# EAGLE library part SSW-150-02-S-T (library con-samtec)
THROUGH-HOLE .025" SQ POST SOCKET Source: Samtec SSW.pdf
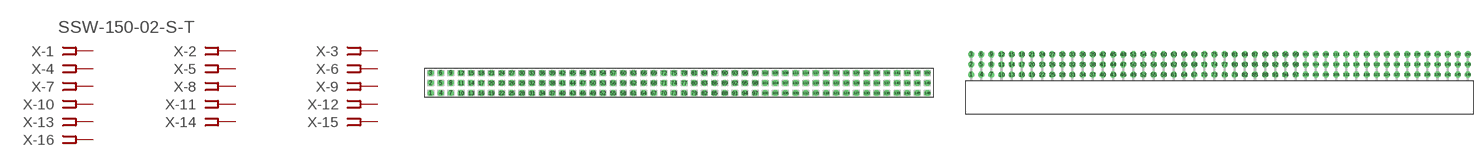
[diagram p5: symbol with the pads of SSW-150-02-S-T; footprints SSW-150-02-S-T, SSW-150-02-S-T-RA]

Designator prefix X; gates -1=FPINV -2=FPIN -3=FPIN -4=FPIN -5=FPIN -6=FPIN -7=FPIN -8=FPIN -9=FPIN -10=FPIN -11=FPIN -12=FPIN -13=FPIN -14=FPIN -15=FPIN -16=FPIN -17=FPIN -18=FPIN -19=FPIN -20=FPIN -21=FPIN -22=FPIN -23=FPIN -24=FPIN -25=FPIN -26=FPIN -27=FPIN -28=FPIN -29=FPIN -30=FPIN -31=FPIN -32=FPIN -33=FPIN -34=FPIN -35=FPIN -36=FPIN -37=FPIN -38=FPIN -39=FPIN -40=FPIN -41=FPIN -42=FPIN -43=FPIN -44=FPIN -45=FPIN -46=FPIN -47=FPIN -48=FPIN -49=FPIN -50=FPIN -51=FPIN -52=FPIN -53=FPIN -54=FPIN -55=FPIN -56=FPIN -57=FPIN -58=FPIN -59=FPIN -60=FPIN -61=FPIN -62=FPIN -63=FPIN -64=FPIN -65=FPIN -66=FPIN -67=FPIN -68=FPIN -69=FPIN -70=FPIN -71=FPIN -72=FPIN -73=FPIN -74=FPIN -75=FPIN -76=FPIN -77=FPIN -78=FPIN -79=FPIN -80=FPIN -81=FPIN -82=FPIN -83=FPIN -84=FPIN -85=FPIN -86=FPIN -87=FPIN -88=FPIN -89=FPIN -90=FPIN -91=FPIN -92=FPIN -93=FPIN -94=FPIN -95=FPIN -96=FPIN -97=FPIN -98=FPIN -99=FPIN -100=FPIN -101=FPIN -102=FPIN -103=FPIN -104=FPIN -105=FPIN -106=FPIN -107=FPIN -108=FPIN -109=FPIN -110=FPIN -111=FPIN -112=FPIN -113=FPIN -114=FPIN -115=FPIN -116=FPIN -117=FPIN -118=FPIN -119=FPIN -120=FPIN -121=FPIN -122=FPIN -123=FPIN -124=FPIN -125=FPIN -126=FPIN -127=FPIN -128=FPIN -129=FPIN -130=FPIN -131=FPIN -132=FPIN -133=FPIN -134=FPIN -135=FPIN -136=FPIN -137=FPIN -138=FPIN -139=FPIN -140=FPIN -141=FPIN -142=FPIN -143=FPIN -144=FPIN -145=FPIN -146=FPIN -147=FPIN -148=FPIN -149=FPIN -150=FPIN

## SSW-150-02-S-T (MPN: SSW-150-02-S-T; OC_FARNELL: unknown; OC_NEWARK: 83P1897)  [SSW-150-02-S-T]
1  -1:1  pas
2  -2:1  pas
3  -3:1  pas
4  -4:1  pas
5  -5:1  pas
6  -6:1  pas
7  -7:1  pas
8  -8:1  pas
9  -9:1  pas
10  -10:1  pas
11  -11:1  pas
12  -12:1  pas
13  -13:1  pas
14  -14:1  pas
15  -15:1  pas
16  -16:1  pas
17  -17:1  pas
18  -18:1  pas
19  -19:1  pas
20  -20:1  pas
21  -21:1  pas
22  -22:1  pas
23  -23:1  pas
24  -24:1  pas
25  -25:1  pas
26  -26:1  pas
27  -27:1  pas
28  -28:1  pas
29  -29:1  pas
30  -30:1  pas
31  -31:1  pas
32  -32:1  pas
33  -33:1  pas
34  -34:1  pas
35  -35:1  pas
36  -36:1  pas
37  -37:1  pas
38  -38:1  pas
39  -39:1  pas
40  -40:1  pas
41  -41:1  pas
42  -42:1  pas
43  -43:1  pas
44  -44:1  pas
45  -45:1  pas
46  -46:1  pas
47  -47:1  pas
48  -48:1  pas
49  -49:1  pas
50  -50:1  pas
51  -51:1  pas
52  -52:1  pas
53  -53:1  pas
54  -54:1  pas
55  -55:1  pas
56  -56:1  pas
57  -57:1  pas
58  -58:1  pas
59  -59:1  pas
60  -60:1  pas
61  -61:1  pas
62  -62:1  pas
63  -63:1  pas
64  -64:1  pas
65  -65:1  pas
66  -66:1  pas
67  -67:1  pas
68  -68:1  pas
69  -69:1  pas
70  -70:1  pas
71  -71:1  pas
72  -72:1  pas
73  -73:1  pas
74  -74:1  pas
75  -75:1  pas
76  -76:1  pas
77  -77:1  pas
78  -78:1  pas
79  -79:1  pas
80  -80:1  pas
81  -81:1  pas
82  -82:1  pas
83  -83:1  pas
84  -84:1  pas
85  -85:1  pas
86  -86:1  pas
87  -87:1  pas
88  -88:1  pas
89  -89:1  pas
90  -90:1  pas
91  -91:1  pas
92  -92:1  pas
93  -93:1  pas
94  -94:1  pas
95  -95:1  pas
96  -96:1  pas
97  -97:1  pas
98  -98:1  pas
99  -99:1  pas
100  -100:1  pas
101  -101:1  pas
102  -102:1  pas
103  -103:1  pas
104  -104:1  pas
105  -105:1  pas
106  -106:1  pas
107  -107:1  pas
108  -108:1  pas
109  -109:1  pas
110  -110:1  pas
111  -111:1  pas
112  -112:1  pas
113  -113:1  pas
114  -114:1  pas
115  -115:1  pas
116  -116:1  pas
117  -117:1  pas
118  -118:1  pas
119  -119:1  pas
120  -120:1  pas
121  -121:1  pas
122  -122:1  pas
123  -123:1  pas
124  -124:1  pas
125  -125:1  pas
126  -126:1  pas
127  -127:1  pas
128  -128:1  pas
129  -129:1  pas
130  -130:1  pas
131  -131:1  pas
132  -132:1  pas
133  -133:1  pas
134  -134:1  pas
135  -135:1  pas
136  -136:1  pas
137  -137:1  pas
138  -138:1  pas
139  -139:1  pas
140  -140:1  pas
141  -141:1  pas
142  -142:1  pas
143  -143:1  pas
144  -144:1  pas
145  -145:1  pas
146  -146:1  pas
147  -147:1  pas
148  -148:1  pas
149  -149:1  pas
150  -150:1  pas

## SSW-150-02-S-TRA (MPN: SSW-150-02-S-T-RA; OC_FARNELL: unknown; OC_NEWARK: 83P1898)  [SSW-150-02-S-T-RA]
Pads as for SSW-150-02-S-T

## Footprint SSW-150-02-S-T (pad centres in mm)
THROUGH-HOLE .025" SQ POST SOCKET Source: Samtec SSW.pdf
drill 1 pad 1.5 octagon: 1 -62.23,-2.54; 2 -62.23,0; 3 -62.23,2.54; 4 -59.69,-2.54; 5 -59.69,0; 6 -59.69,2.54; 7 -57.15,-2.54; 8 -57.15,0; 9 -57.15,2.54; 10 -54.61,-2.54; 11 -54.61,0; 12 -54.61,2.54; 13 -52.07,-2.54; 14 -52.07,0; 15 -52.07,2.54; 16 -49.53,-2.54; 17 -49.53,0; 18 -49.53,2.54; 19 -46.99,-2.54; 20 -46.99,0; 21 -46.99,2.54; 22 -44.45,-2.54; 23 -44.45,0; 24 -44.45,2.54; 25 -41.91,-2.54; 26 -41.91,0; 27 -41.91,2.54; 28 -39.37,-2.54; 29 -39.37,0; 30 -39.37,2.54; 31 -36.83,-2.54; 32 -36.83,0; 33 -36.83,2.54; 34 -34.29,-2.54; 35 -34.29,0; 36 -34.29,2.54; 37 -31.75,-2.54; 38 -31.75,0; 39 -31.75,2.54; 40 -29.21,-2.54; 41 -29.21,0; 42 -29.21,2.54; 43 -26.67,-2.54; 44 -26.67,0; 45 -26.67,2.54; 46 -24.13,-2.54; 47 -24.13,0; 48 -24.13,2.54; 49 -21.59,-2.54; 50 -21.59,0; 51 -21.59,2.54; 52 -19.05,-2.54; 53 -19.05,0; 54 -19.05,2.54; 55 -16.51,-2.54; 56 -16.51,0; 57 -16.51,2.54; 58 -13.97,-2.54; 59 -13.97,0; 60 -13.97,2.54; 61 -11.43,-2.54; 62 -11.43,0; 63 -11.43,2.54; 64 -8.89,-2.54; 65 -8.89,0; 66 -8.89,2.54; 67 -6.35,-2.54; 68 -6.35,0; 69 -6.35,2.54; 70 -3.81,-2.54; 71 -3.81,0; 72 -3.81,2.54; 73 -1.27,-2.54; 74 -1.27,0; 75 -1.27,2.54; 76 1.27,-2.54; 77 1.27,0; 78 1.27,2.54; 79 3.81,-2.54; 80 3.81,0; 81 3.81,2.54; 82 6.35,-2.54; 83 6.35,0; 84 6.35,2.54; 85 8.89,-2.54; 86 8.89,0; 87 8.89,2.54; 88 11.43,-2.54; 89 11.43,0; 90 11.43,2.54; 91 13.97,-2.54; 92 13.97,0; 93 13.97,2.54; 94 16.51,-2.54; 95 16.51,0; 96 16.51,2.54; 97 19.05,-2.54; 98 19.05,0; 99 19.05,2.54; 100 21.59,-2.54; 101 21.59,0; 102 21.59,2.54; 103 24.13,-2.54; 104 24.13,0; 105 24.13,2.54; 106 26.67,-2.54; 107 26.67,0; 108 26.67,2.54; 109 29.21,-2.54; 110 29.21,0; 111 29.21,2.54; 112 31.75,-2.54; 113 31.75,0; 114 31.75,2.54; 115 34.29,-2.54; 116 34.29,0; 117 34.29,2.54; 118 36.83,-2.54; 119 36.83,0; 120 36.83,2.54; 121 39.37,-2.54; 122 39.37,0; 123 39.37,2.54; 124 41.91,-2.54; 125 41.91,0; 126 41.91,2.54; 127 44.45,-2.54; 128 44.45,0; 129 44.45,2.54; 130 46.99,-2.54; 131 46.99,0; 132 46.99,2.54; 133 49.53,-2.54; 134 49.53,0; 135 49.53,2.54; 136 52.07,-2.54; 137 52.07,0; 138 52.07,2.54; 139 54.61,-2.54; 140 54.61,0; 141 54.61,2.54; 142 57.15,-2.54; 143 57.15,0; 144 57.15,2.54; 145 59.69,-2.54; 146 59.69,0; 147 59.69,2.54; 148 62.23,-2.54; 149 62.23,0; 150 62.23,2.54

## Footprint SSW-150-02-S-T-RA (pad centres in mm)
THROUGH-HOLE .025" SQ POST SOCKET Source: http://www.samtec.com
drill 1 pad 1.5 octagon: 1 -62.23,1.524; 2 -62.23,4.064; 3 -62.23,6.604; 4 -59.69,1.524; 5 -59.69,4.064; 6 -59.69,6.604; 7 -57.15,1.524; 8 -57.15,4.064; 9 -57.15,6.604; 10 -54.61,1.524; 11 -54.61,4.064; 12 -54.61,6.604; 13 -52.07,1.524; 14 -52.07,4.064; 15 -52.07,6.604; 16 -49.53,1.524; 17 -49.53,4.064; 18 -49.53,6.604; 19 -46.99,1.524; 20 -46.99,4.064; 21 -46.99,6.604; 22 -44.45,1.524; 23 -44.45,4.064; 24 -44.45,6.604; 25 -41.91,1.524; 26 -41.91,4.064; 27 -41.91,6.604; 28 -39.37,1.524; 29 -39.37,4.064; 30 -39.37,6.604; 31 -36.83,1.524; 32 -36.83,4.064; 33 -36.83,6.604; 34 -34.29,1.524; 35 -34.29,4.064; 36 -34.29,6.604; 37 -31.75,1.524; 38 -31.75,4.064; 39 -31.75,6.604; 40 -29.21,1.524; 41 -29.21,4.064; 42 -29.21,6.604; 43 -26.67,1.524; 44 -26.67,4.064; 45 -26.67,6.604; 46 -24.13,1.524; 47 -24.13,4.064; 48 -24.13,6.604; 49 -21.59,1.524; 50 -21.59,4.064; 51 -21.59,6.604; 52 -19.05,1.524; 53 -19.05,4.064; 54 -19.05,6.604; 55 -16.51,1.524; 56 -16.51,4.064; 57 -16.51,6.604; 58 -13.97,1.524; 59 -13.97,4.064; 60 -13.97,6.604; 61 -11.43,1.524; 62 -11.43,4.064; 63 -11.43,6.604; 64 -8.89,1.524; 65 -8.89,4.064; 66 -8.89,6.604; 67 -6.35,1.524; 68 -6.35,4.064; 69 -6.35,6.604; 70 -3.81,1.524; 71 -3.81,4.064; 72 -3.81,6.604; 73 -1.27,1.524; 74 -1.27,4.064; 75 -1.27,6.604; 76 1.27,1.524; 77 1.27,4.064; 78 1.27,6.604; 79 3.81,1.524; 80 3.81,4.064; 81 3.81,6.604; 82 6.35,1.524; 83 6.35,4.064; 84 6.35,6.604; 85 8.89,1.524; 86 8.89,4.064; 87 8.89,6.604; 88 11.43,1.524; 89 11.43,4.064; 90 11.43,6.604; 91 13.97,1.524; 92 13.97,4.064; 93 13.97,6.604; 94 16.51,1.524; 95 16.51,4.064; 96 16.51,6.604; 97 19.05,1.524; 98 19.05,4.064; 99 19.05,6.604; 100 21.59,1.524; 101 21.59,4.064; 102 21.59,6.604; 103 24.13,1.524; 104 24.13,4.064; 105 24.13,6.604; 106 26.67,1.524; 107 26.67,4.064; 108 26.67,6.604; 109 29.21,1.524; 110 29.21,4.064; 111 29.21,6.604; 112 31.75,1.524; 113 31.75,4.064; 114 31.75,6.604; 115 34.29,1.524; 116 34.29,4.064; 117 34.29,6.604; 118 36.83,1.524; 119 36.83,4.064; 120 36.83,6.604; 121 39.37,1.524; 122 39.37,4.064; 123 39.37,6.604; 124 41.91,1.524; 125 41.91,4.064; 126 41.91,6.604; 127 44.45,1.524; 128 44.45,4.064; 129 44.45,6.604; 130 46.99,1.524; 131 46.99,4.064; 132 46.99,6.604; 133 49.53,1.524; 134 49.53,4.064; 135 49.53,6.604; 136 52.07,1.524; 137 52.07,4.064; 138 52.07,6.604; 139 54.61,1.524; 140 54.61,4.064; 141 54.61,6.604; 142 57.15,1.524; 143 57.15,4.064; 144 57.15,6.604; 145 59.69,1.524; 146 59.69,4.064; 147 59.69,6.604; 148 62.23,1.524; 149 62.23,4.064; 150 62.23,6.604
